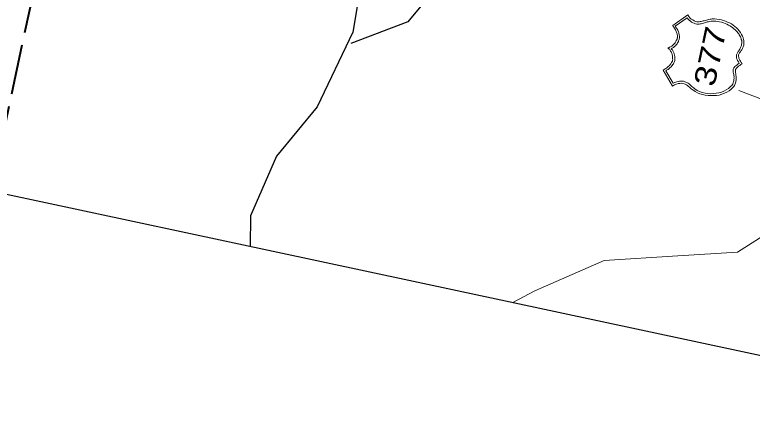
# Model space of a CAD drawing. Extents: x 2363411 to 2369126, y 6976878 to 6988319.
# Drawn here: x 2365871.2 to 2366047.6, y 6976877.7 to 6976977 of the extents above; entities that cross this region are included whole.
import ezdxf

# ---------------------------------------------------------------- set-up
doc = ezdxf.new("R2010")
doc.units = 0
doc.header["$LTSCALE"] = 2
doc.linetypes.add('LONG_DASHED', pattern=[7.5, 6, -1.5])
doc.layers.add('62', color=7, linetype='Continuous', lineweight=13)
doc.layers.add('63', color=7, linetype='Continuous', lineweight=13)

msp = doc.modelspace()

# ---------------------------------------------------------------- linework, layer by layer
at = {"layer": '62', "lineweight": 25}
for points in [[(2365678.211, 6976974.92), (2366133.213, 6976877.7), (2366227.156, 6977317.368), (2365772.152, 6977414.588)], [(2365956.96, 6977002.524), (2365952.078, 6976972.894), (2365943.56, 6976954.995), (2365933.815, 6976943.2), (2365927.549, 6976928.939), (2365927.531, 6976921.648)], [(2365979.497, 6977001.917), (2365975.737, 6976988.088), (2365965.212, 6976975.356), (2365951.615, 6976970.187)]]:
    msp.add_lwpolyline(points, dxfattribs=at)
at = {"layer": '62', "linetype": 'LONG_DASHED', "lineweight": 40}
msp.add_lwpolyline([(2365804.964, 6976956.79), (2365867.37, 6976943.454), (2365903.697, 6977113.468), (2365841.291, 6977126.802), (2365804.897, 6976956.481)], dxfattribs=at)
at = {"layer": '62'}
for points in [[(2366028.515, 6976959.967), (2366026.271, 6976963.782), (2366026.485, 6976963.92), (2366026.747, 6976964.071), (2366026.938, 6976964.214), (2366027.131, 6976964.357), (2366027.322, 6976964.5), (2366027.498, 6976964.671), (2366027.665, 6976964.819), (2366027.837, 6976964.967), (2366027.962, 6976965.124), (2366028.086, 6976965.282), (2366028.216, 6976965.458), (2366028.298, 6976965.627), (2366028.384, 6976965.815), (2366028.46, 6976965.961), (2366028.504, 6976966.158), (2366028.546, 6976966.355), (2366028.53, 6976966.498), (2366028.519, 6976966.662), (2366028.534, 6976966.843), (2366028.529, 6976967.028), (2366028.478, 6976967.223), (2366028.449, 6976967.413), (2366028.396, 6976967.584), (2366028.346, 6976967.779), (2366028.25, 6976967.985), (2366028.172, 6976968.163), (2366028.051, 6976968.349), (2366027.974, 6976968.527), (2366027.85, 6976968.692), (2366027.718, 6976968.833), (2366027.562, 6976968.958), (2366027.404, 6976969.086), (2366027.604, 6976969.158), (2366027.807, 6976969.252), (2366028.007, 6976969.323), (2366028.173, 6976969.452), (2366028.356, 6976969.55), (2366028.523, 6976969.698), (2366028.695, 6976969.845), (2366028.837, 6976969.974), (2366028.961, 6976970.134), (2366029.111, 6976970.288), (2366029.218, 6976970.472), (2366029.323, 6976970.631), (2366029.413, 6976970.845), (2366029.491, 6976970.988), (2366029.58, 6976971.198), (2366029.646, 6976971.391), (2366029.678, 6976971.545), (2366029.693, 6976971.724), (2366029.684, 6976971.888), (2366029.682, 6976972.099), (2366029.626, 6976972.27), (2366029.576, 6976972.465), (2366029.52, 6976972.638), (2366029.447, 6976972.838), (2366029.37, 6976973.014), (2366029.281, 6976973.242), (2366029.182, 6976973.425), (2366029.066, 6976973.631), (2366028.944, 6976973.821), (2366028.81, 6976974.054), (2366028.686, 6976974.22), (2366028.547, 6976974.433), (2366032.154, 6976977), (2366032.402, 6976976.647), (2366032.67, 6976976.291), (2366033.002, 6976976.011), (2366033.344, 6976975.779), (2366033.691, 6976975.566), (2366034.028, 6976975.424), (2366034.288, 6976975.346), (2366034.512, 6976975.323), (2366034.671, 6976975.311), (2366034.889, 6976975.357), (2366035.076, 6976975.384), (2366035.318, 6976975.424), (2366035.564, 6976975.489), (2366035.806, 6976975.553), (2366036.071, 6976975.611), (2366036.341, 6976975.691), (2366036.635, 6976975.765), (2366036.904, 6976975.846), (2366037.22, 6976975.916), (2366037.484, 6976975.974), (2366037.744, 6976976.01), (2366038.022, 6976976.021), (2366038.285, 6976976.057), (2366038.532, 6976976.026), (2366039.121, 6976975.994), (2366039.659, 6976975.924), (2366040.186, 6976975.812), (2366040.705, 6976975.654), (2366041.203, 6976975.502), (2366041.684, 6976975.283), (2366042.121, 6976975.075), (2366042.574, 6976974.817), (2366043.001, 6976974.544), (2366043.415, 6976974.224)], [(2366043.941, 6976972.915), (2366043.734, 6976973.144), (2366043.491, 6976973.402), (2366043.198, 6976973.649), (2366042.925, 6976973.869), (2366042.582, 6976974.103), (2366042.243, 6976974.338), (2366041.902, 6976974.57), (2366041.505, 6976974.771), (2366041.107, 6976974.948), (2366040.68, 6976975.107), (2366040.232, 6976975.272), (2366039.77, 6976975.369), (2366039.277, 6976975.431), (2366038.849, 6976975.474), (2366038.467, 6976975.512), (2366038.096, 6976975.5), (2366037.748, 6976975.482), (2366037.39, 6976975.421), (2366037.074, 6976975.35), (2366036.764, 6976975.3), (2366036.467, 6976975.203), (2366036.166, 6976975.084), (2366035.924, 6976975.019), (2366035.653, 6976974.94), (2366035.387, 6976974.882), (2366035.121, 6976974.822), (2366034.863, 6976974.81), (2366034.607, 6976974.795), (2366034.333, 6976974.807), (2366034.025, 6976974.872), (2366033.703, 6976974.988), (2366033.388, 6976975.125), (2366033.076, 6976975.284), (2366032.776, 6976975.487), (2366032.51, 6976975.748), (2366032.265, 6976976.009), (2366032.032, 6976976.313), (2366029.136, 6976974.285), (2366029.28, 6976974.093), (2366029.406, 6976973.927), (2366029.526, 6976973.742), (2366029.647, 6976973.554), (2366029.743, 6976973.352), (2366029.837, 6976973.145), (2366029.908, 6976972.948), (2366029.98, 6976972.747), (2366030.026, 6976972.53), (2366030.098, 6976972.331), (2366030.123, 6976972.117), (2366030.135, 6976971.955), (2366030.157, 6976971.744), (2366030.147, 6976971.584), (2366030.14, 6976971.447), (2366030.128, 6976971.288), (2366030.076, 6976971.139), (2366030.033, 6976970.94), (2366029.972, 6976970.769), (2366029.912, 6976970.597), (2366029.805, 6976970.414), (2366029.705, 6976970.274), (2366029.596, 6976970.09), (2366029.471, 6976969.933), (2366029.35, 6976969.797), (2366029.219, 6976969.617), (2366029.077, 6976969.488), (2366028.912, 6976969.361), (2366028.764, 6976969.209), (2366028.587, 6976969.132), (2366028.401, 6976969.01), (2366028.197, 6976968.915), (2366028.344, 6976968.746), (2366028.474, 6976968.604), (2366028.552, 6976968.426), (2366028.656, 6976968.266), (2366028.714, 6976968.115), (2366028.796, 6976967.96), (2366028.869, 6976967.759), (2366028.933, 6976967.629), (2366028.961, 6976967.44), (2366029.016, 6976967.267), (2366029.03, 6976967.105), (2366029.061, 6976966.936), (2366029.049, 6976966.775), (2366029.084, 6976966.611), (2366029.07, 6976966.43), (2366029.058, 6976966.27), (2366029.041, 6976966.09), (2366028.994, 6976965.869), (2366028.912, 6976965.702), (2366028.821, 6976965.493), (2366028.714, 6976965.309), (2366028.578, 6976965.107), (2366028.448, 6976964.928), (2366028.3, 6976964.776), (2366028.147, 6976964.6), (2366027.97, 6976964.411), (2366027.821, 6976964.256), (2366027.635, 6976964.135), (2366027.438, 6976963.97), (2366027.252, 6976963.848)], [(2366043.415, 6976974.224), (2366043.787, 6976973.916), (2366044.12, 6976973.544), (2366044.455, 6976973.176), (2366044.731, 6976972.746), (2366045.008, 6976972.319), (2366045.259, 6976971.875), (2366045.366, 6976971.621), (2366045.433, 6976971.4), (2366045.491, 6976971.134), (2366045.534, 6976970.896), (2366045.578, 6976970.68), (2366045.552, 6976970.454), (2366045.567, 6976970.198), (2366045.548, 6976969.995), (2366045.522, 6976969.772), (2366045.454, 6976969.555), (2366045.389, 6976969.362), (2366045.325, 6976969.169), (2366045.211, 6976968.963), (2366045.157, 6976968.813), (2366045.05, 6976968.629), (2366044.922, 6976968.472), (2366044.823, 6976968.332), (2366044.744, 6976968.167), (2366044.623, 6976968.031), (2366044.524, 6976967.893), (2366044.468, 6976967.741), (2366044.392, 6976967.596), (2366044.309, 6976967.429), (2366044.293, 6976967.249), (2366044.299, 6976967.063), (2366044.327, 6976966.873), (2366044.395, 6976966.65), (2366044.469, 6976966.45), (2366044.593, 6976966.172), (2366044.721, 6976965.914), (2366044.939, 6976965.638), (2366045.163, 6976965.29), (2366044.849, 6976965.105), (2366044.576, 6976964.91), (2366044.315, 6976964.759), (2366044.139, 6976964.588), (2366043.947, 6976964.445), (2366043.822, 6976964.29), (2366043.723, 6976964.149), (2366043.646, 6976964.004), (2366043.6, 6976963.9), (2366043.562, 6976963.724), (2366043.54, 6976963.612), (2366043.572, 6976963.445), (2366043.567, 6976963.307), (2366043.56, 6976963.172), (2366043.615, 6976963.001), (2366043.625, 6976962.833), (2366043.669, 6976962.711), (2366043.674, 6976962.526), (2366043.705, 6976962.335), (2366043.732, 6976962.147), (2366043.713, 6976961.943), (2366043.695, 6976961.762), (2366043.719, 6976961.549), (2366043.699, 6976961.349), (2366043.654, 6976961.127), (2366043.614, 6976960.952), (2366043.567, 6976960.731), (2366043.495, 6976960.492), (2366043.385, 6976960.309), (2366043.295, 6976960.099), (2366043.138, 6976959.902), (2366042.982, 6976959.706), (2366042.565, 6976959.266), (2366042.04, 6976958.87), (2366041.487, 6976958.529), (2366040.896, 6976958.242), (2366040.271, 6976958.007), (2366039.66, 6976957.839), (2366038.996, 6976957.75), (2366038.317, 6976957.688), (2366037.65, 6976957.694), (2366036.994, 6976957.74), (2366036.34, 6976957.812), (2366035.702, 6976957.948), (2366035.057, 6976958.154), (2366034.486, 6976958.392), (2366033.886, 6976958.705), (2366033.382, 6976959.039), (2366033.183, 6976959.176), (2366032.964, 6976959.337), (2366032.772, 6976959.515), (2366032.563, 6976959.723), (2366032.321, 6976959.89), (2366032.085, 6976960.077), (2366031.826, 6976960.272), (2366031.555, 6976960.399), (2366031.254, 6976960.508), (2366030.925, 6976960.579), (2366030.594, 6976960.651), (2366030.24, 6976960.611), (2366029.863, 6976960.577), (2366029.427, 6976960.461)], [(2366026.909, 6976963.648), (2366028.682, 6976960.645), (2366029.095, 6976960.855), (2366029.513, 6976960.972), (2366029.86, 6976961.082), (2366030.194, 6976961.15), (2366030.543, 6976961.168), (2366030.861, 6976961.145), (2366031.135, 6976961.133), (2366031.413, 6976961.029), (2366031.689, 6976960.923), (2366031.939, 6976960.8), (2366032.209, 6976960.65), (2366032.448, 6976960.484), (2366032.667, 6976960.321), (2366032.898, 6976960.11), (2366033.107, 6976959.908), (2366033.338, 6976959.695), (2366033.851, 6976959.287), (2366034.423, 6976958.958), (2366034.985, 6976958.676), (2366035.629, 6976958.469), (2366036.284, 6976958.307), (2366036.93, 6976958.191), (2366037.611, 6976958.16), (2366038.26, 6976958.181), (2366038.918, 6976958.249), (2366039.592, 6976958.383), (2366040.203, 6976958.549), (2366040.807, 6976958.79), (2366041.348, 6976959.065), (2366041.877, 6976959.388), (2366042.328, 6976959.778), (2366042.762, 6976960.189), (2366042.807, 6976960.296), (2366042.897, 6976960.393), (2366042.951, 6976960.539), (2366042.991, 6976960.716), (2366043.045, 6976960.864), (2366043.099, 6976961.015), (2366043.137, 6976961.193), (2366043.156, 6976961.393), (2366043.173, 6976961.576), (2366043.21, 6976961.75), (2366043.204, 6976961.937), (2366043.219, 6976962.116), (2366043.213, 6976962.301), (2366043.201, 6976962.465), (2366043.169, 6976962.634), (2366043.176, 6976962.769), (2366043.119, 6976962.943), (2366043.082, 6976963.09), (2366043.045, 6976963.235), (2366043.008, 6976963.382), (2366043.001, 6976963.567), (2366043.001, 6976963.682), (2366042.991, 6976963.846), (2366043.029, 6976964.022), (2366043.104, 6976964.165), (2366043.192, 6976964.355), (2366043.296, 6976964.517), (2366043.438, 6976964.648), (2366043.617, 6976964.841), (2366043.885, 6976965.013), (2366044.16, 6976965.228), (2366044.475, 6976965.414), (2366044.256, 6976965.784), (2366044.07, 6976966.1), (2366043.941, 6976966.357), (2366043.839, 6976966.632), (2366043.798, 6976966.87), (2366043.77, 6976967.06), (2366043.769, 6976967.268), (2366043.81, 6976967.466), (2366043.848, 6976967.644), (2366043.925, 6976967.787), (2366044.029, 6976967.949), (2366044.11, 6976968.116), (2366044.236, 6976968.273), (2366044.363, 6976968.43), (2366044.443, 6976968.597), (2366044.596, 6976968.771), (2366044.681, 6976968.961), (2366044.797, 6976969.168), (2366044.861, 6976969.361), (2366044.924, 6976969.552), (2366044.97, 6976969.773), (2366045.018, 6976969.994), (2366045.04, 6976970.198), (2366045.063, 6976970.422), (2366045.045, 6976970.655), (2366045.043, 6976970.864), (2366044.952, 6976971.09), (2366044.911, 6976971.328), (2366044.818, 6976971.534), (2366044.734, 6976971.781), (2366044.598, 6976972.016), (2366044.444, 6976972.256), (2366044.326, 6976972.467), (2366044.117, 6976972.673), (2366043.941, 6976972.915)], [(2365990.291, 6976908.24), (2365995.575, 6976910.999), (2366012.158, 6976918.295), (2366029.791, 6976919.405), (2366044.007, 6976920.255), (2366053.944, 6976926.599), (2366070.505, 6976938.615), (2366078.644, 6976946.012), (2366091.784, 6976957.768), (2366110.586, 6976965.533)], [(2366027.252, 6976963.848), (2366027.069, 6976963.75), (2366026.909, 6976963.648)], [(2366029.427, 6976960.461), (2366028.991, 6976960.258), (2366028.515, 6976959.967)], [(2366044.33, 6976958.911), (2366056.7, 6976954.245), (2366068.834, 6976948.245), (2366077.828, 6976934.335), (2366086.801, 6976917.439), (2366099.873, 6976897.735), (2366106.059, 6976883.502)]]:
    msp.add_lwpolyline(points, dxfattribs=at)
at = {"layer": '63', "lineweight": 25}
for points in [[(2365678.211, 6976974.92), (2366133.213, 6976877.7), (2366227.156, 6977317.368), (2365772.152, 6977414.588)], [(2365956.96, 6977002.524), (2365952.078, 6976972.894), (2365943.56, 6976954.995), (2365933.815, 6976943.2), (2365927.549, 6976928.939), (2365927.531, 6976921.648)], [(2365979.497, 6977001.917), (2365975.737, 6976988.088), (2365965.212, 6976975.356), (2365951.615, 6976970.187)]]:
    msp.add_lwpolyline(points, dxfattribs=at)
at = {"layer": '63', "linetype": 'LONG_DASHED', "lineweight": 40}
msp.add_lwpolyline([(2365804.964, 6976956.79), (2365867.37, 6976943.454), (2365903.697, 6977113.468), (2365841.291, 6977126.802), (2365804.897, 6976956.481)], dxfattribs=at)
at = {"layer": '63'}
for points in [[(2366028.515, 6976959.967), (2366026.271, 6976963.782), (2366026.485, 6976963.92), (2366026.747, 6976964.071), (2366026.938, 6976964.214), (2366027.131, 6976964.357), (2366027.322, 6976964.5), (2366027.498, 6976964.671), (2366027.665, 6976964.819), (2366027.837, 6976964.967), (2366027.962, 6976965.124), (2366028.086, 6976965.282), (2366028.216, 6976965.458), (2366028.298, 6976965.627), (2366028.384, 6976965.815), (2366028.46, 6976965.961), (2366028.504, 6976966.158), (2366028.546, 6976966.355), (2366028.53, 6976966.498), (2366028.519, 6976966.662), (2366028.534, 6976966.843), (2366028.529, 6976967.028), (2366028.478, 6976967.223), (2366028.449, 6976967.413), (2366028.396, 6976967.584), (2366028.346, 6976967.779), (2366028.25, 6976967.985), (2366028.172, 6976968.163), (2366028.051, 6976968.349), (2366027.974, 6976968.527), (2366027.85, 6976968.692), (2366027.718, 6976968.833), (2366027.562, 6976968.958), (2366027.404, 6976969.086), (2366027.604, 6976969.158), (2366027.807, 6976969.252), (2366028.007, 6976969.323), (2366028.173, 6976969.452), (2366028.356, 6976969.55), (2366028.523, 6976969.698), (2366028.695, 6976969.845), (2366028.837, 6976969.974), (2366028.961, 6976970.134), (2366029.111, 6976970.288), (2366029.218, 6976970.472), (2366029.323, 6976970.631), (2366029.413, 6976970.845), (2366029.491, 6976970.988), (2366029.58, 6976971.198), (2366029.646, 6976971.391), (2366029.678, 6976971.545), (2366029.693, 6976971.724), (2366029.684, 6976971.888), (2366029.682, 6976972.099), (2366029.626, 6976972.27), (2366029.576, 6976972.465), (2366029.52, 6976972.638), (2366029.447, 6976972.838), (2366029.37, 6976973.014), (2366029.281, 6976973.242), (2366029.182, 6976973.425), (2366029.066, 6976973.631), (2366028.944, 6976973.821), (2366028.81, 6976974.054), (2366028.686, 6976974.22), (2366028.547, 6976974.433), (2366032.154, 6976977), (2366032.402, 6976976.647), (2366032.67, 6976976.291), (2366033.002, 6976976.011), (2366033.344, 6976975.779), (2366033.691, 6976975.566), (2366034.028, 6976975.424), (2366034.288, 6976975.346), (2366034.512, 6976975.323), (2366034.671, 6976975.311), (2366034.889, 6976975.357), (2366035.076, 6976975.384), (2366035.318, 6976975.424), (2366035.564, 6976975.489), (2366035.806, 6976975.553), (2366036.071, 6976975.611), (2366036.341, 6976975.691), (2366036.635, 6976975.765), (2366036.904, 6976975.846), (2366037.22, 6976975.916), (2366037.484, 6976975.974), (2366037.744, 6976976.01), (2366038.022, 6976976.021), (2366038.285, 6976976.057), (2366038.532, 6976976.026), (2366039.121, 6976975.994), (2366039.659, 6976975.924), (2366040.186, 6976975.812), (2366040.705, 6976975.654), (2366041.203, 6976975.502), (2366041.684, 6976975.283), (2366042.121, 6976975.075), (2366042.574, 6976974.817), (2366043.001, 6976974.544), (2366043.415, 6976974.224)], [(2366043.941, 6976972.915), (2366043.734, 6976973.144), (2366043.491, 6976973.402), (2366043.198, 6976973.649), (2366042.925, 6976973.869), (2366042.582, 6976974.103), (2366042.243, 6976974.338), (2366041.902, 6976974.57), (2366041.505, 6976974.771), (2366041.107, 6976974.948), (2366040.68, 6976975.107), (2366040.232, 6976975.272), (2366039.77, 6976975.369), (2366039.277, 6976975.431), (2366038.849, 6976975.474), (2366038.467, 6976975.512), (2366038.096, 6976975.5), (2366037.748, 6976975.482), (2366037.39, 6976975.421), (2366037.074, 6976975.35), (2366036.764, 6976975.3), (2366036.467, 6976975.203), (2366036.166, 6976975.084), (2366035.924, 6976975.019), (2366035.653, 6976974.94), (2366035.387, 6976974.882), (2366035.121, 6976974.822), (2366034.863, 6976974.81), (2366034.607, 6976974.795), (2366034.333, 6976974.807), (2366034.025, 6976974.872), (2366033.703, 6976974.988), (2366033.388, 6976975.125), (2366033.076, 6976975.284), (2366032.776, 6976975.487), (2366032.51, 6976975.748), (2366032.265, 6976976.009), (2366032.032, 6976976.313), (2366029.136, 6976974.285), (2366029.28, 6976974.093), (2366029.406, 6976973.927), (2366029.526, 6976973.742), (2366029.647, 6976973.554), (2366029.743, 6976973.352), (2366029.837, 6976973.145), (2366029.908, 6976972.948), (2366029.98, 6976972.747), (2366030.026, 6976972.53), (2366030.098, 6976972.331), (2366030.123, 6976972.117), (2366030.135, 6976971.955), (2366030.157, 6976971.744), (2366030.147, 6976971.584), (2366030.14, 6976971.447), (2366030.128, 6976971.288), (2366030.076, 6976971.139), (2366030.033, 6976970.94), (2366029.972, 6976970.769), (2366029.912, 6976970.597), (2366029.805, 6976970.414), (2366029.705, 6976970.274), (2366029.596, 6976970.09), (2366029.471, 6976969.933), (2366029.35, 6976969.797), (2366029.219, 6976969.617), (2366029.077, 6976969.488), (2366028.912, 6976969.361), (2366028.764, 6976969.209), (2366028.587, 6976969.132), (2366028.401, 6976969.01), (2366028.197, 6976968.915), (2366028.344, 6976968.746), (2366028.474, 6976968.604), (2366028.552, 6976968.426), (2366028.656, 6976968.266), (2366028.714, 6976968.115), (2366028.796, 6976967.96), (2366028.869, 6976967.759), (2366028.933, 6976967.629), (2366028.961, 6976967.44), (2366029.016, 6976967.267), (2366029.03, 6976967.105), (2366029.061, 6976966.936), (2366029.049, 6976966.775), (2366029.084, 6976966.611), (2366029.07, 6976966.43), (2366029.058, 6976966.27), (2366029.041, 6976966.09), (2366028.994, 6976965.869), (2366028.912, 6976965.702), (2366028.821, 6976965.493), (2366028.714, 6976965.309), (2366028.578, 6976965.107), (2366028.448, 6976964.928), (2366028.3, 6976964.776), (2366028.147, 6976964.6), (2366027.97, 6976964.411), (2366027.821, 6976964.256), (2366027.635, 6976964.135), (2366027.438, 6976963.97), (2366027.252, 6976963.848)], [(2366043.415, 6976974.224), (2366043.787, 6976973.916), (2366044.12, 6976973.544), (2366044.455, 6976973.176), (2366044.731, 6976972.746), (2366045.008, 6976972.319), (2366045.259, 6976971.875), (2366045.366, 6976971.621), (2366045.433, 6976971.4), (2366045.491, 6976971.134), (2366045.534, 6976970.896), (2366045.578, 6976970.68), (2366045.552, 6976970.454), (2366045.567, 6976970.198), (2366045.548, 6976969.995), (2366045.522, 6976969.772), (2366045.454, 6976969.555), (2366045.389, 6976969.362), (2366045.325, 6976969.169), (2366045.211, 6976968.963), (2366045.157, 6976968.813), (2366045.05, 6976968.629), (2366044.922, 6976968.472), (2366044.823, 6976968.332), (2366044.744, 6976968.167), (2366044.623, 6976968.031), (2366044.524, 6976967.893), (2366044.468, 6976967.741), (2366044.392, 6976967.596), (2366044.309, 6976967.429), (2366044.293, 6976967.249), (2366044.299, 6976967.063), (2366044.327, 6976966.873), (2366044.395, 6976966.65), (2366044.469, 6976966.45), (2366044.593, 6976966.172), (2366044.721, 6976965.914), (2366044.939, 6976965.638), (2366045.163, 6976965.29), (2366044.849, 6976965.105), (2366044.576, 6976964.91), (2366044.315, 6976964.759), (2366044.139, 6976964.588), (2366043.947, 6976964.445), (2366043.822, 6976964.29), (2366043.723, 6976964.149), (2366043.646, 6976964.004), (2366043.6, 6976963.9), (2366043.562, 6976963.724), (2366043.54, 6976963.612), (2366043.572, 6976963.445), (2366043.567, 6976963.307), (2366043.56, 6976963.172), (2366043.615, 6976963.001), (2366043.625, 6976962.833), (2366043.669, 6976962.711), (2366043.674, 6976962.526), (2366043.705, 6976962.335), (2366043.732, 6976962.147), (2366043.713, 6976961.943), (2366043.695, 6976961.762), (2366043.719, 6976961.549), (2366043.699, 6976961.349), (2366043.654, 6976961.127), (2366043.614, 6976960.952), (2366043.567, 6976960.731), (2366043.495, 6976960.492), (2366043.385, 6976960.309), (2366043.295, 6976960.099), (2366043.138, 6976959.902), (2366042.982, 6976959.706), (2366042.565, 6976959.266), (2366042.04, 6976958.87), (2366041.487, 6976958.529), (2366040.896, 6976958.242), (2366040.271, 6976958.007), (2366039.66, 6976957.839), (2366038.996, 6976957.75), (2366038.317, 6976957.688), (2366037.65, 6976957.694), (2366036.994, 6976957.74), (2366036.34, 6976957.812), (2366035.702, 6976957.948), (2366035.057, 6976958.154), (2366034.486, 6976958.392), (2366033.886, 6976958.705), (2366033.382, 6976959.039), (2366033.183, 6976959.176), (2366032.964, 6976959.337), (2366032.772, 6976959.515), (2366032.563, 6976959.723), (2366032.321, 6976959.89), (2366032.085, 6976960.077), (2366031.826, 6976960.272), (2366031.555, 6976960.399), (2366031.254, 6976960.508), (2366030.925, 6976960.579), (2366030.594, 6976960.651), (2366030.24, 6976960.611), (2366029.863, 6976960.577), (2366029.427, 6976960.461)], [(2366026.909, 6976963.648), (2366028.682, 6976960.645), (2366029.095, 6976960.855), (2366029.513, 6976960.972), (2366029.86, 6976961.082), (2366030.194, 6976961.15), (2366030.543, 6976961.168), (2366030.861, 6976961.145), (2366031.135, 6976961.133), (2366031.413, 6976961.029), (2366031.689, 6976960.923), (2366031.939, 6976960.8), (2366032.209, 6976960.65), (2366032.448, 6976960.484), (2366032.667, 6976960.321), (2366032.898, 6976960.11), (2366033.107, 6976959.908), (2366033.338, 6976959.695), (2366033.851, 6976959.287), (2366034.423, 6976958.958), (2366034.985, 6976958.676), (2366035.629, 6976958.469), (2366036.284, 6976958.307), (2366036.93, 6976958.191), (2366037.611, 6976958.16), (2366038.26, 6976958.181), (2366038.918, 6976958.249), (2366039.592, 6976958.383), (2366040.203, 6976958.549), (2366040.807, 6976958.79), (2366041.348, 6976959.065), (2366041.877, 6976959.388), (2366042.328, 6976959.778), (2366042.762, 6976960.189), (2366042.807, 6976960.296), (2366042.897, 6976960.393), (2366042.951, 6976960.539), (2366042.991, 6976960.716), (2366043.045, 6976960.864), (2366043.099, 6976961.015), (2366043.137, 6976961.193), (2366043.156, 6976961.393), (2366043.173, 6976961.576), (2366043.21, 6976961.75), (2366043.204, 6976961.937), (2366043.219, 6976962.116), (2366043.213, 6976962.301), (2366043.201, 6976962.465), (2366043.169, 6976962.634), (2366043.176, 6976962.769), (2366043.119, 6976962.943), (2366043.082, 6976963.09), (2366043.045, 6976963.235), (2366043.008, 6976963.382), (2366043.001, 6976963.567), (2366043.001, 6976963.682), (2366042.991, 6976963.846), (2366043.029, 6976964.022), (2366043.104, 6976964.165), (2366043.192, 6976964.355), (2366043.296, 6976964.517), (2366043.438, 6976964.648), (2366043.617, 6976964.841), (2366043.885, 6976965.013), (2366044.16, 6976965.228), (2366044.475, 6976965.414), (2366044.256, 6976965.784), (2366044.07, 6976966.1), (2366043.941, 6976966.357), (2366043.839, 6976966.632), (2366043.798, 6976966.87), (2366043.77, 6976967.06), (2366043.769, 6976967.268), (2366043.81, 6976967.466), (2366043.848, 6976967.644), (2366043.925, 6976967.787), (2366044.029, 6976967.949), (2366044.11, 6976968.116), (2366044.236, 6976968.273), (2366044.363, 6976968.43), (2366044.443, 6976968.597), (2366044.596, 6976968.771), (2366044.681, 6976968.961), (2366044.797, 6976969.168), (2366044.861, 6976969.361), (2366044.924, 6976969.552), (2366044.97, 6976969.773), (2366045.018, 6976969.994), (2366045.04, 6976970.198), (2366045.063, 6976970.422), (2366045.045, 6976970.655), (2366045.043, 6976970.864), (2366044.952, 6976971.09), (2366044.911, 6976971.328), (2366044.818, 6976971.534), (2366044.734, 6976971.781), (2366044.598, 6976972.016), (2366044.444, 6976972.256), (2366044.326, 6976972.467), (2366044.117, 6976972.673), (2366043.941, 6976972.915)], [(2365990.291, 6976908.24), (2365995.575, 6976910.999), (2366012.158, 6976918.295), (2366029.791, 6976919.405), (2366044.007, 6976920.255), (2366053.944, 6976926.599), (2366070.505, 6976938.615), (2366078.644, 6976946.012), (2366091.784, 6976957.768), (2366110.586, 6976965.533)], [(2366027.252, 6976963.848), (2366027.069, 6976963.75), (2366026.909, 6976963.648)], [(2366029.427, 6976960.461), (2366028.991, 6976960.258), (2366028.515, 6976959.967)], [(2366044.33, 6976958.911), (2366056.7, 6976954.245), (2366068.834, 6976948.245), (2366077.828, 6976934.335), (2366086.801, 6976917.439), (2366099.873, 6976897.735), (2366106.059, 6976883.502)]]:
    msp.add_lwpolyline(points, dxfattribs=at)

# ---------------------------------------------------------------- texts
at = {"layer": '62', "width": 1.25}
msp.add_text('377', height=5.099, rotation=77.939, dxfattribs=at).set_placement((2366038.497, 6976959.605))
at = {"layer": '63', "width": 1.25}
msp.add_text('377', height=5.099, rotation=77.939, dxfattribs=at).set_placement((2366038.497, 6976959.605))

doc.saveas('drawing.dxf')
